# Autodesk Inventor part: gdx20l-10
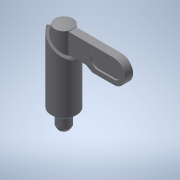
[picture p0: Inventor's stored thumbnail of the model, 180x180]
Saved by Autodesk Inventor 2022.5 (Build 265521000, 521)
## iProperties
Created: 2016-12
Part Number: gdx20l-10
Material: 一般
Document SubType Name: Modeling
Designer: imaocorp
Density: 1 g/cm^3
Appearance: 既定
Author: imaocorp
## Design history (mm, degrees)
node "gdx20l-10.x_t1"
node "gdx20l-10"
node "Base1"
